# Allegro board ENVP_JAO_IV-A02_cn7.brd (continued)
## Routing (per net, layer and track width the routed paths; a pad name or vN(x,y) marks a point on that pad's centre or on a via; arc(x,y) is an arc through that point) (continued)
PS_1V8_SNUB: length 1.7
  TOP w0.508: C68.1 82.31,80.01 R58.2
PS_12_CS: length 14.4
  BOTTOM w0.254: R515.2 78.93,115.62 78.93,116.46 74.42,120.97 74.42,122.17 72.39,124.21 71.37,124.21 71.12,124.46 R94.1
  vias: v1(69.85,124.97) v1(69.85,124.33) v1(69.85,123.7) v1(71.5,127.76) v1(71.5,127.13) v1(71.5,126.49) v1(72.14,127.76) v1(72.77,127.76)
PS_12V_BIAS: length 11.4
  TOP w0.203: U8.21 75.2,113.62 74.78,114.05 74.55,114.05
  TOP w0.508: 74.55,114.05 73.53,115.06 C114.1 73.53,115.42 72.64,116.31 v1(72.64,116.33) ; R842.2 v1(78.17,118.36)
  L3-IN1 w0.508: v1(78.17,118.36) 77.28,117.47 73.79,117.47 v1(72.64,116.33)
PS_12V_BODE: length 1.1
  TOP w0.254: R92.2 C107.1
PS_12V_BOOT1: length 7.5
  TOP w0.203: U8.23 74.05,112.74
  TOP w0.508: 74.05,112.74 72.02,114.77 C111.2 72.02,115.68 71.63,116.08 71.63,118.44 D3.1
PS_12V_BOOT2: length 5.6
  TOP w0.203: U8.17 77.2,113.77 77.34,113.91 77.34,114.06
  TOP w0.508: C113.2 76.7,116.71 D2.1 76.14,116.27 76.39,116.01 76.39,114.94 76.77,114.55 77.09,114.55 77.34,114.3 77.34,114.06
PS_12V_COMP: length 3.4
  TOP w0.254: U8.6 77.2,108.98 77.34,108.84 77.34,107.65 C108.1 R92.1
PS_12V_CS: length 3.4
  TOP w0.254: v1(79.88,112.14) 79.87,112.13 U8.13
  BOTTOM w0.254: v1(79.88,112.14) 79.78,112.04 79.42,112.04 C109.1 78.99,112.47 78.99,113.12 R515.1
PS_12V_CSG: length 4.6
  TOP w0.254: U8.12 79.76,111.63 v1(79.88,111.51)
  BOTTOM w0.254: v1(79.88,111.51) 79.8,111.59 78.97,111.59 C109.2 78.49,112.47 78.49,113.06 R815.1
PS_12V_DITH: length 2.5
  TOP w0.254: C104.2 74.17,107.86 75.2,108.9 U8.2
PS_12V_FB: length 4.4
  TOP w0.254: R104.1 R103.1 80.59,108.51 80.01,109.09 78.46,109.09 78.2,109.35 U8.8
PS_12V_HDRV1: length 23.8
  TOP w0.203: U8.24 73.72,112.13 v1(73.25,112.6)
  TOP w0.508: v1(61.59,128.02) 61.16,127.58 R97.2
  BOTTOM w0.508: v1(73.25,112.6) 69.22,116.64 69.22,118.62 65.02,122.81 65.02,127.51 64.52,128.02 v1(61.59,128.02)
PS_12V_HDRV2: length 11.9
  TOP w0.203: 78.12,113.97 77.7,113.56 U8.16
  TOP w0.508: v1(77.09,115.19) 77.62,115.19 78.12,114.69 78.12,113.97 ; R99.2 79.88,122.62 v1(79.69,122.43)
  L3-IN1 w0.508: v1(77.09,115.19) 79.69,117.79 v1(79.69,122.43)
PS_12V_HG1: length 2.2
  TOP w0.508: Q12.1 61.98,127.38 61.27,126.67 R97.1
PS_12V_HG2: length 1.6
  TOP w0.508: R99.1 79.71,124.03 78.87,123.19 Q13.1
PS_12V_LDRV1: length 21.2
  TOP w0.203: 74.43,113.28 U8.22
  TOP w0.508: v1(74.17,113.54) 74.43,113.28 ; R98.2 v1(70.61,128.27)
  BOTTOM w0.508: v1(70.61,128.27) 68.58,128.27 67.82,127.51 67.82,123.19 68.2,122.81 68.45,122.81 68.83,122.43 68.83,120.52 70.23,119.13 70.23,117.49 v1(74.17,113.54)
PS_12V_LDRV2: length 10.3
  TOP w0.203: 76.7,113.79 U8.18
  TOP w0.254: v1(76.71,113.92) 76.7,113.91 76.7,113.79
  TOP w0.508: R100.2 72.2,120.71 v1(72.52,120.4)
  BOTTOM w0.508: v1(72.52,120.4) 74.3,118.62 74.3,115.19 75.56,113.92 v1(76.71,113.92)
PS_12V_LG1: length 2
  TOP w0.508: Q12.8 69.72,127.38 70.43,126.67 R98.1
PS_12V_LG2: length 1.3
  TOP w0.508: Q13.8 72.2,122.85 R100.1
PS_12V_MODE: length 2.8
  TOP w0.254: R102.1 73.03,107.48 74.7,109.16 U8.1
PS_12V_OUT: length 22.7
  TOP w0.254: 81.12,124.73 C117.1 81.13,124.49 82.55,123.06 85.47,123.06 87,121.54 87,117.86 81.03,111.89 R101.1 81.66,110.82 81.66,110.06 R103.2
  vias: v1(76.96,131.95) v1(76.96,131.32) v1(76.96,129.67) v1(76.96,129.03) v1(79.5,126.87) v1(79.5,126.24) v1(79.5,125.6) v1(79.5,124.97) v1(80.14,126.87) v1(80.14,126.24) v1(80.14,125.6) v1(80.14,124.97) v1(80.52,131.83) v1(80.52,130.05) v1(80.52,129.41) v1(80.52,128.14) v1(81.15,131.83) v1(81.15,130.05) v1(81.15,129.41) v1(81.15,128.14)
PS_12V_RT: length 2.3
  TOP w0.254: 75.7,108.79 U8.3
  TOP w0.508: R91.2 75.31,107.81 75.7,108.2 75.7,108.79
PS_12V_SLOPE: length 2.2
  TOP w0.254: C105.2 76.21,107.63 76.21,108.91 76.2,108.92 U8.4
PS_12V_SS: length 2.1
  TOP w0.254: U8.5 76.7,108.72 v1(76.83,108.58)
  BOTTOM w0.254: C106.2 76.35,108.58 v1(76.83,108.58)
PS_12V_SW1: length 13
  TOP w0.203: 73.06,111.84 73.27,111.63 U8.25
  TOP w0.508: 73.06,111.84 70.47,114.43 C111.1 70.47,116.34 69.72,117.09 69.72,118.87 67.92,120.68 R69.1
PS_12V_SW2: length 11
  TOP w0.203: 78.4,113.36 78.31,113.28 U8.15
  TOP w0.508: 78.4,113.36 78.49,113.36 78.88,113.76 C113.1 78.88,116.4 76.96,118.31 76.96,119.89 76.45,120.4 74.68,120.4 74.17,120.9
PS_12V_VCC: length 6.3
  TOP w0.203: 75.5,114.05 75.5,113.86 75.7,113.65 U8.20
  TOP w0.508: D3.2 74.74,118.24 D2.2 74.74,115.62 C112.1 74.79,114.76 75.5,114.05
PS_12V_VIN: length 6
  TOP w0.254: 73.2,110.45 73.38,110.63 U8.27
  TOP w0.508: R93.2 71.36,107.98 C110.1 71.5,107.96 73.2,109.66 73.2,110.45
PS_12V_VIN_D: length 1.7
  TOP w0.508: D1.1 69.79,105.34 69.6,105.54 R93.1
PS_12V_VOSNS: length 2.3
  TOP w0.254: U8.9 80.61,110.13 R101.2
PS_20_CS: length 13
  BOTTOM w0.254: R479.1 36.13,110.82 36.13,111.3 38.42,113.59 38.42,115.95 37.78,116.59 34.61,116.59 34.23,116.97 R698.1 34.23,118.61
  vias: v1(31.81,119.38) v1(31.81,118.75) v1(31.81,118.11) v1(31.81,117.41) v1(34.16,121.16) v1(34.8,121.16) v1(35.43,121.16) v1(36.07,121.16) v1(36.64,119.38) v1(36.64,118.75) v1(36.64,118.11) v1(36.64,117.41) v1(37.08,121.16) v1(37.72,121.16)
PS_20V_BIAS: length 16.4
  TOP w0.203: U124.21 31.1,108.6 30.56,109.14
  TOP w0.508: 30.56,109.14 30.18,109.52 C510.1 30.29,110.43 v1(30.73,110.87) ; R841.2 41.27,113.16 v1(40.64,113.79)
  L6-IN2 w0.508: v1(40.64,113.79) 37.72,110.87 v1(30.73,110.87)
PS_20V_BODE: length 1.1
  TOP w0.254: C513.1 R688.2
PS_20V_BOOT1: length 5.8
  TOP w0.203: 29.95,107.85 U124.23
  TOP w0.508: D28.1 27.7,112.14 C506.2 27.7,110.1 29.95,107.85
PS_20V_BOOT2: length 8
  TOP w0.203: 33.27,109.09 33.1,108.92 U124.17
  TOP w0.508: 33.27,109.09 34.54,110.36 36.94,110.36 C507.2 37.07,111.25 D29.1
PS_20V_COMP: length 5.1
  TOP w0.254: R688.1 35.89,102.23 C512.1 35.13,103 33.78,103 33.1,103.68 U124.6
PS_20V_CS: length 4.7
  TOP w0.254: U124.13 35.78,107.1 36.2,106.68 v1(36.2,106.55)
  BOTTOM w0.254: v1(36.2,106.55) 36.13,106.62 36.13,106.92 C505.2 36.13,107.96 36.13,108.38 R479.2
PS_20V_CSG: length 3.8
  TOP w0.254: v1(35.56,106.55) 35.52,106.6 U124.12
  BOTTOM w0.254: v1(35.56,106.55) 35.62,106.62 35.62,106.92 C505.1 35.62,107.96 35.62,108.32 R513.2
PS_20V_DITH: length 2.4
  TOP w0.254: C497.2 30.48,103.25 31.1,103.87 U124.2
PS_20V_FB: length 4.4
  TOP w0.254: R697.1 36.7,103.56 36.7,104.47 R694.2 36.32,104.65 35.94,104.27 34.28,104.27 U124.8
PS_20V_HDRV1: length 22.8
  TOP w0.203: v1(29.21,107.57) 29.21,107.37 29.48,107.1 U124.24
  TOP w0.508: v1(24.13,125.22) 23.88,125.48 R689.1
  BOTTOM w0.508: v1(24.13,125.22) 24.13,110.62 27.18,107.57 v1(29.21,107.57)
PS_20V_HDRV2: length 41.2
  TOP w0.203: U124.16 33.6,108.53 34.04,108.97 34.16,108.97
  TOP w0.508: R692.1 v1(47.88,138.18) ; v1(37.47,109.47) 34.67,109.47 34.16,108.97
  L3-IN1 w0.508: v1(47.88,138.18) 48.77,137.29 48.77,127 48.26,126.49 44.45,126.49 43.94,125.98 43.94,115.95 v1(37.47,109.47)
PS_20V_HG1_2: length 3.1
  TOP w0.508: R689.2 23.88,128.27 23.25,128.9 Q64.1
PS_20V_HG2: length 1.8
  TOP w0.508: R692.2 46.19,138.09 Q68.1
PS_20V_LDRV1: length 16.9
  TOP w0.203: v1(30.15,108.58) 30.35,108.58 30.6,108.34 U124.22
  TOP w0.508: v1(33.15,121.16) 33.15,120.47 R690.1
  BOTTOM w0.508: v1(33.15,121.16) 30.86,121.16 29.72,120.02 29.72,109.02 v1(30.15,108.58)
PS_20V_LDRV2: length 8.8
  TOP w0.203: U124.18 32.6,109.05 32.64,109.09
  TOP w0.508: R691.1 35.56,114.99 35.56,111.51 35.18,111.12 34.29,111.12 32.64,109.47 32.64,109.09
PS_20V_LG1: length 1.4
  TOP w0.508: R690.2 32.25,120.46 U126.4
PS_20V_LG2: length 1.9
  TOP w0.508: R691.2 36.99,116.15 Q65.4
PS_20V_MODE: length 2.7
  TOP w0.254: R693.1 29.34,102.87 30.6,104.13 U124.1
PS_20V_RT: length 2.1
  TOP w0.254: 31.6,103.76 U124.3
  TOP w0.508: 31.6,103.76 31.6,102.34 R687.2
PS_20V_SLOPE: length 2.4
  TOP w0.254: U124.4 32.1,103.89 32.11,103.88 32.11,102.92 32.72,102.31 C511.1
PS_20V_SS: length 3.2
  TOP w0.254: U124.5 32.6,103.57 34.04,102.13 C509.2
PS_20V_SW1: length 11
  TOP w0.203: U124.25 29.17,106.6 28.96,106.81
  TOP w0.508: R844.1 25.15,113.91 25.15,111.24 C506.1 26.15,109.61 28.96,106.81
PS_20V_SW2: length 11.6
  TOP w0.203: 34.29,108.33 34.21,108.25 U124.15
  TOP w0.508: 34.29,108.33 34.92,108.33 35.18,108.58 37.72,108.58 38.23,109.09 38.23,110.1 C507.1 38.99,110.49 39.75,111.25 39.75,114.01 C620.2
PS_20V_VCC: length 6.9
  TOP w0.203: 31.37,109.09 31.5,108.97 31.5,108.58 31.6,108.48 U124.20
  TOP w0.508: 31.37,109.09 31.37,110.38 C514.1 31.5,110.5 31.5,112.15 D28.2 32,112.65 D29.2
PS_20V_VOSNS: length 2.4
  TOP w0.254: U124.9 35.12,105.1 35.81,105.79 R696.1
RS232_RD1: length 4.2
  BOTTOM w0.102: 23.68,95.21 23.4,95.21 23.24,95.38 23.24,96.25 22.91,96.58 22.91,97.2 22.48,97.62 22.01,97.62 R610.1
RS232_RD2: length 3.7
  BOTTOM w0.102: 23.68,79.72 23.4,79.72 23.24,79.88 23.24,80.75 22.25,81.75 22.01,81.75 R665.1
RS232_TD1: length 2.3
  BOTTOM w0.102: R612.1 21.56,94.21 23.68,94.21
RS232_TD2: length 2.3
  BOTTOM w0.102: 23.68,78.72 21.62,78.72 R667.1
RS485_D1-: length 4.4
  BOTTOM w0.102: R608.1 22.01,97.83 22.57,97.83 23.11,97.28 23.11,96.66 23.38,96.39 24.26,96.39 24.42,96.23 24.42,95.96
RS485_D2-: length 3.9
  BOTTOM w0.102: R663.1 22.01,81.95 22.33,81.95 23.38,80.9 24.26,80.9 24.42,80.74 24.42,80.46
RTS1: length 26.7
  TOP w0.102: v1(21.84,91.82) 21.84,91.42 D52.2 19.15,89.79 18.9,90.04 18.9,91.53 17.72,92.71 14.73,92.71 12.06,90.04 12.06,86.49 10.03,84.45 9.14,84.45 6.8,86.8 CN35.16
  BOTTOM w0.102: 23.68,92.21 22.24,92.21 v1(21.84,91.82)
RTS2: length 20.9
  TOP w0.102: v1(21.97,75.95) 21.97,74.8 21.08,73.91 D57.2 15.37,78.76 15.37,85.2 CN35.7
  BOTTOM w0.102: 23.68,76.72 22.74,76.72 v1(21.97,75.95)
RX1/D1+: length 20.9
  TOP w0.102: CN35.11 9.64,89.42 9.74,89.52 10.56,89.52 14.51,93.47 17.27,93.47 18.54,94.74 18.54,97.63 18.75,97.84 18.92,97.84 19.27,97.5 19.27,96.3 19.43,96.14 D53.2 20.21,97.14 v1(19.94,97.41)
  BOTTOM w0.102: v1(19.94,97.41) 20.15,97.62 20.52,97.62 20.62,97.52 R610.2
RX2/D2+: length 15.7
  TOP w0.102: v1(19.77,81.53) 20.21,81.09 D58.2 19.43,80.26 19.18,80.52 19.18,81.56 19.08,81.66 18.8,81.66 18.54,81.92 18.54,86.03 17.84,86.73 17.84,89.09 17.41,89.52 16.65,89.52 16.55,89.42 CN35.2
  BOTTOM w0.102: v1(19.77,81.53) 19.99,81.75 20.15,81.75 R665.2
SNN_EFM8SB10_P0_5: length 3.2
  BOTTOM w0.102: TP49.1 95,64.52 94.51,65 92.17,65 92.16,65.01
SNN_USBC2_MUX_CTRL_N: length 2.5
  TOP w0.102: R559.2 52.25,70.41 52.68,70.85 U107.28
SNN_VBUS_MON_P2: length 3.1
  TOP w0.102: R848.1 56.7,76.96 54.79,75.05 U107.37
SNN_VCONN_MON_P2: length 3.3
  TOP w0.254: U107.25 51.19,70.83 49.32,68.96 R849.1
SP339_5V: length 33.6
  TOP w0.254: 16.58,62.36 17.26,62.36 17.27,62.36 v1(17.4,62.36)
  TOP w0.381: 29.67,91.19 30.58,91.19 v1(30.6,91.21)
  BOTTOM w0.254: 24.19,73.6 24.42,73.82 24.42,74.48 ; 29.66,91.21 v1(30.6,91.21) ; 24.42,89.97 24.42,88.94 v1(24,88.52) ; C454.2 28.7,97.79 27.92,97.01 27.92,95.96 ; 24.92,95.96 24.92,97.25 v1(24.64,97.54) ; v1(30.61,75.41) 30.3,75.72 29.66,75.72 ; C473.2 24.92,82.57 24.92,80.46 ; 27.92,80.46 v1(27.92,81.39)
  BOTTOM w0.508: C454.2 28.24,98.22 28.07,98.04 v1(27.94,98.04) ; v1(24.13,82.17) 24.56,82.6 C473.2 ; v1(17.4,62.36) 16.76,62.36 16.65,62.24 16.51,62.24 16.46,62.29 16.46,63.63 18.92,63.63 19.81,64.52 19.81,69.98 21.34,71.5 22.23,71.5 22.73,72.01 22.73,73.15 v1(22.99,73.41) 24,73.41 24.19,73.6
  vias: v1(30.61,81.28) v1(30.61,80.64) v1(31.24,81.28) v1(31.24,80.64)
SP339_UART2_RTS: length 80.7
  TOP w0.102: R304.2 89.48,97.92 89.48,96.72 v1(89.79,96.42)
  L6-IN2 w0.089: v1(43.94,78.49) 43.94,79.06 44.22,79.34 47.77,79.34 48.11,78.99 52.32,78.99 52.96,78.36 56.19,78.36 59.21,75.33 86.14,75.33 87.22,76.41 89.3,76.41 89.97,77.08 89.97,79.91 90.4,80.35 90.4,84.52 89.12,85.81 89.12,89.61 88.44,90.29 88.44,92.88 89.15,93.6 89.15,93.85 88.98,94.03 88.98,95.07 89.79,95.89 v1(89.79,96.42)
  BOTTOM w0.102: 37.01,75.93 39.35,75.93 39.37,75.95 40.77,75.95 41.4,76.58 42.55,76.58 43.94,77.98 v1(43.94,78.49)
SP339_UART2_RX: length 76.7
  TOP w0.102: v1(88.65,93.73) 91.24,93.73 R625.2
  L6-IN2 w0.089: v1(88.65,93.73) 88.12,93.2 88.12,90.15 88.8,89.47 88.8,85.68 89.03,85.45 89.03,77.49 88.27,76.73 87.09,76.73 86.01,75.65 59.35,75.65 55.68,79.31 48.25,79.31 47.9,79.65 44.09,79.65 43.62,79.19 43.62,78.8 v1(43.31,78.49)
  BOTTOM w0.102: 37.01,76.33 37.87,76.33 38.89,77.34 40.77,77.34 41.45,78.03 42.85,78.03 v1(43.31,78.49)
SP339_UART2_TX: length 77.3
  TOP w0.102: R624.2 91.74,93.09 v1(89.28,93.09)
  L6-IN2 w0.089: v1(89.28,93.09) 89.43,92.94 89.43,85.94 90.72,84.66 90.72,80.21 90.28,79.78 90.28,76.95 89.43,76.09 87.35,76.09 86.27,75.01 59.08,75.01 56.65,77.44 55.84,77.44 55.24,78.04 43.05,78.04 42.8,78.3 42.8,78.74 42.29,79.25 v1(42.27,79.25)
  BOTTOM w0.102: 37.01,76.73 37.74,76.73 38.17,77.16 38.17,77.54 39.24,78.61 40.69,78.61 41.33,79.25 v1(42.27,79.25)
SRC_ON_D: length 3.9
  TOP w0.254: Q20.1 62.93,103.75 62.93,102.72 Q19.3 62.79,102.73 R120.2
SRC_SW_G: length 7.3
  TOP w0.508: R120.1 61.42,103.76 C621.2 v1(60.2,105.16) 60.2,105.87 R119.2 60.2,106.22 Q21.4
  BOTTOM w0.508: v1(60.2,105.16) 60.35,105 C126.2
SYS_RST_IN_N: length 131.8
  TOP w0.102: v1(8.64,41.27) 7.62,41.27 6.55,40.21 6.48,40.21 ; v1(87.76,71.12) 90.14,71.12 90.65,70.61 94.64,70.61 v1(97.84,73.81)
  L6-IN2 w0.089: v1(8.64,41.27) 10.67,43.31 10.67,45.86 12.57,47.76 12.57,64.36 22.57,74.36 23.18,74.36 24.68,75.86 31.84,75.86 32.55,75.15 34.32,75.15 35.13,74.34 42.52,74.34 43.39,73.47 47.4,73.47 47.4,73.47 47.75,73.47 47.75,73.47 48.01,73.21 48.01,71.78 48.91,70.88 49.2,70.88 49.2,70.89 55.48,70.89 56.43,69.93 68.21,69.93 70.42,72.14 86.73,72.14 v1(87.76,71.12)
  BOTTOM w0.102: v1(97.84,73.81) 97.82,73.79 97.41,73.79 97.1,74.09 97.1,76 96.79,76.31 96.79,77.48 97.36,78.05 97.36,78.87 ; Q40.1 86.35,70.6 86.87,71.12 v1(87.76,71.12)
SYS_RST_IN_Q: length 5
  BOTTOM w0.102: Q41.1 89.14,68.82 88.33,68.01 Q40.3 87,67.06 87.2,66.85 R469.2
TX1: length 18.5
  TOP w0.102: v1(21.84,92.58) 21.46,92.96 D51.2 14.66,92.96 11.84,90.14 11.84,86.58 10.73,85.47 CN35.12
  BOTTOM w0.102: R612.2 21.46,92.96 v1(21.84,92.58)
TX2: length 13
  TOP w0.102: CN35.3 17.65,84.37 17.65,78.61 19.18,77.09 D56.2 21.72,77.09 v1(21.84,76.96)
  BOTTOM w0.102: R667.2 21.46,77.34 v1(21.84,76.96)
UPHY0_RX4_N:
  vias: v2(164.09,103.66) v3(164.09,103.66) v4(163.47,103.71) v5(122.76,95.02) v6(122.76,95.02)
UPHY0_RX4_P:
  vias: v2(164.09,103.15) v3(164.09,103.15) v4(163.47,103.1) v5(122.25,95.02) v6(122.25,95.02)
UPHY0_RX5_N:
  vias: v2(165.14,101.9) v3(165.14,101.9) v4(120.2,90.05) v5(120.25,90.52) v6(120.25,90.52)
UPHY0_RX5_P:
  vias: v2(165.14,101.39) v3(165.14,101.39) v4(120.81,90.05) v5(120.76,90.52) v6(120.76,90.52)
UPHY0_SF_PCIE1_CLK_N:
  vias: v2(154.58,65.46) v3(154.58,65.46) v4(115.9,79.76) v5(107.38,94.68) v6(107.38,94.68)
UPHY0_SF_PCIE1_CLK_P:
  vias: v2(154.58,65.97) v3(154.58,65.97) v4(115.29,79.76) v5(106.88,94.68) v6(106.88,94.68)
UPHY0_TX5_N:
  vias: v2(170.98,100.44) v3(170.98,100.44) v4(165.65,106.16) v5(122.25,101.02) v6(122.25,101.02)
UPHY0_TX5_P:
  vias: v2(170.98,99.94) v3(170.98,99.94) v4(165.65,106.77) v5(122.76,101.02) v6(122.76,101.02)
UPHY1_REFCLK0_N:
  vias: v5(124.19,99.1) v5(154.56,128.02) v6(124.19,99.1) v6(154.56,128.02)
UPHY1_REFCLK0_P:
  vias: v5(124.7,99.1) v5(155.07,128.02) v6(124.7,99.1) v6(155.07,128.02)
UPHY2_REFCLK2_N:
  vias: v2(124.11,96.14) v3(124.11,96.14) v4(124.34,97.61) v5(126.25,98) v6(126.25,98)
UPHY2_REFCLK2_P:
  vias: v2(124.62,96.14) v3(124.62,96.14) v4(124.94,97.61) v5(126.76,98) v6(126.76,98)
UPHY_RX10_N:
  vias: v2(163.81,98.9) v3(163.81,98.9) v4(142.8,91.02) v5(142.25,92.01) v6(142.25,92.01)
UPHY_RX10_P:
  vias: v2(163.81,98.39) v3(163.81,98.39) v4(143.41,91.02) v5(142.76,92.01) v6(142.76,92.01)
UPHY_RX11_N:
  vias: v2(163.62,95.9) v3(163.62,95.9) v4(143.31,97.02) v5(143.36,96.53) v6(143.36,96.53)
UPHY_RX11_P:
  vias: v2(163.62,95.39) v3(163.62,95.39) v4(143.92,97.02) v5(143.87,96.53) v6(143.87,96.53)
UPHY_TX6_N:
  vias: v2(116.11,45.55) v3(116.11,45.55) v4(116.06,46.5) v5(136.78,97.66) v6(136.78,97.66)
UPHY_TX6_P:
  vias: v2(116.62,45.55) v3(116.62,45.55) v4(116.67,46.5) v5(136.27,97.66) v6(136.27,97.66)
UPHY_TX9_N:
  vias: v2(94.81,136.51) v3(94.81,136.51) v4(94.86,136.06) v5(140.6,102.02) v6(140.6,102.02)
UPHY_TX9_P:
  vias: v2(94.3,136.51) v3(94.3,136.51) v4(94.25,136.06) v5(140.09,102.02) v6(140.09,102.02)
USB2_1_N:
  vias: v7(144.84,94.93)
USB2_1_P:
  vias: v7(144.18,94.93)
USB2_3_N:
  vias: v2(83.36,39.3) v3(83.36,39.3) v4(83.82,39.35) v5(144.75,99.06) v6(144.75,99.06)
USB2_3_P:
  vias: v2(83.36,38.79) v3(83.36,38.79) v4(83.82,38.74) v5(144.25,99.06) v6(144.25,99.06)
USBC1_CC1_DUT: length 6.5
  TOP w0.203: v1(46.23,80.77) 46.18,80.72 C422.1 46.81,77.98 49.53,77.98 49.68,77.82 U107.9
USBC1_CC2_DUT: length 5
  TOP w0.203: U107.7 50.68,78.12 52.2,79.63 C423.1 52.2,79.88 51.56,80.52 v1(51.56,81.41)
USBC1_MUX_CTRL_N: length 4.4
  TOP w0.102: v1(55.24,69.72) 55.24,69.01 R558.2 54.56,69.6 53.72,69.6 53.47,69.85 53.47,70.61 53.19,70.89 U107.29
USBC1_ORIENTATION: length 0.9
  TOP w0.102: v1(47.57,73.05) U107.18
USBC1_VBUS: length 5.1
  TOP w0.508: R555.1 41.27,75.18 39.5,73.41 v1(37.97,73.41)
  vias: v1(30.48,67.18) v1(30.48,66.55) v1(31.11,67.18) v1(31.11,66.55) v1(31.75,67.18) v1(31.75,66.55) v1(32.46,67.18) v1(33.15,67.18) v1(33.78,67.18) v1(33.78,66.55) v1(39.12,102.23) v1(39.12,101.6) v1(39.75,102.23) v1(39.75,101.6) v1(176.75,114.68) v1(176.75,114.05) v1(177.38,114.68) v1(177.38,114.05) v1(177.74,113.47) v1(178.02,114.68) v1(178.02,114.05) v1(178.37,113.47) v1(178.69,114.68) v1(178.69,114.05) v1(179.63,107.29) v1(179.63,106.65) v1(180.34,107.94) v1(180.28,107.29) v1(180.28,106.65) v1(180.57,106.08) v1(180.92,107.25) v1(180.92,106.62) v1(181.48,110.32) v1(181.56,107.26) v1(181.57,106.62) v1(182.11,110.12)
VCONN_MON_P1: length 4.6
  TOP w0.102: R553.2 R554.1 C424.1 46.33,72.54 U107.19
XRES: length 4.7
  TOP w0.102: R552.2 C421.1 46.48,76.33 47.12,76.96 49.02,76.96 49.19,77.13 U107.10
N7364585: length 3.1
  TOP w0.254: R31.1 R32.2 68.58,82.5 U2.11
N7364615: length 5
  TOP w0.254: U2.16 69.84,86.63
  TOP w0.508: R30.2 72.82,87.43 C46.1 72.54,87.5 70.93,87.5 70.05,86.63 69.84,86.63
N7364639: length 2.3
  TOP w0.254: C58.1 R44.1 R43.2
N7364653: length 4.1
  TOP w0.254: U2.9 67.58,83.96 67.44,83.82
  TOP w0.508: R46.2 65.98,82.37 C60.1 66.55,82.56 66.55,82.93 67.44,83.82
N7364665: length 5.1
  TOP w0.254: U2.12 69.08,84.09 70.79,82.37 C59.1 R47.1 R45.2
N7364675: length 3
  TOP w0.254: R48.1 70.61,83.44 69.69,84.37 U2.13
N7364759: length 2
  TOP w0.508: R33.1 66.55,90.55 v1(66.29,90.81)
  BOTTOM w0.508: C47.1 66.79,90.31 v1(66.29,90.81)
N7364853: length 9.6
  TOP w0.254: R48.2 72.71,83.55 R49.1 73.91,83.06 73.53,82.68 C62.1 74.3,81.42 74.3,79.24 C56.2 73.53,78.47 C58.2 R44.2
N7364927: length 5.6
  TOP w0.254: 66.16,85.48 U2.7
  TOP w0.762: R40.2 63.75,87.76 66.04,85.48 66.16,85.48
N7364931: length 3.8
  TOP w0.254: U2.2 68.58,87.69 69.98,89.09 C55.1 R39.2
N7365093: length 23.1
  TOP w0.254: C56.1 71.75,78.74 69.29,76.28 65.46,76.28 62.48,79.25 62.48,88.02 R42.2
N7365097: length 2
  TOP w0.508: C57.1 61.99,90.22 61.02,91.19 R41.2
N7366211: length 2.5
  TOP w0.254: U2.4 67.58,87.36 67.44,87.5
  TOP w0.508: 67.44,87.5 67.44,87.76 66.55,88.65 R33.2
N7366215: length 3.4
  TOP w0.254: 66.8,87 66.8,86.64 U2.5
  TOP w0.762: R35.2 65.28,88.52 66.8,87
N7366231: length 2.3
  TOP w0.254: 68.08,87.88 U2.3
  TOP w0.508: 68.08,87.88 68.08,88.82 R36.2
N7371396: length 1.8
  TOP w0.254: U3.8 81.14,83.55 81.28,83.69
  TOP w0.508: C66.2 81.41,83.95 81.28,83.82 81.28,83.69
N7372642: length 17.3
  TOP w0.254: R55.1 86.74,87.25 88.77,85.22 88.77,77.85 88.52,77.6 86.87,77.6
  vias: v1(83.69,78.93) v1(83.69,78.17) v1(83.69,77.41)
N7382435: length 2.4
  TOP w0.254: 68.57,66.15 68.57,66.41 69.6,67.44 C82.2
N7382555: length 22
  TOP w0.254: R66.1 83.77,70.41 84.33,69.85 84.33,65.53 83.06,64.26 R64.1
N7394854:
  vias: v1(126.82,43.64)
N7434344: length 5
  TOP w0.102: Q14.6 70.37,112.26 ; 70.37,112.26 70.48,112.14 70.76,112.14 70.87,112.24 Q14.5 ; 70.37,112.26 69.85,111.74 69.85,111.12 69.09,110.36 69.09,109.65 R107.2
N7802848: length 5.5
  TOP w0.254: C380.2 R705.2 93.14,87.76 93.14,85.9 92.71,85.47 92.71,84.71
N7804391: length 2.1
  BOTTOM w0.102: R462.1 90.73,77.55 90.93,77.34 90.93,76.71 91.17,76.47 U77.6
N7854424: length 2.3
  BOTTOM w0.102: R521.1 53.54,83.57 52.96,84.15 52.96,84.84 53.21,85.08 U97.4
N7855347: length 3.2
  BOTTOM w0.102: R523.1 51.05,83.36 51.05,84.84 50.79,85.1 U99.4
N7856574: length 2.7
  TOP w0.102: U102.6 49.13,87.64 48.9,87.88 48.13,87.88 47.5,87.25 R525.2
N7893694: length 1.5
  TOP w0.102: U104.6 58.94,81.55 59.18,81.79 59.89,81.79 R526.2
N8090559: length 2.3
  BOTTOM w0.102: C456.2 26.31,96.7 26.42,96.6 26.42,95.96
N8090595: length 2.3
  BOTTOM w0.102: 27.42,95.96 27.42,97.22 27.23,97.41 C456.1
N8090599: length 3.6
  BOTTOM w0.102: C459.2 25.83,98.83 25.83,96.62 25.92,96.53 25.92,95.96
N8090635: length 6.3
  BOTTOM w0.102: 28.42,95.96 28.42,96.97 29.31,97.87 29.31,99.44 28.98,99.77 27.69,99.77 C459.1
N8090819: length 2.3
  BOTTOM w0.102: 25.92,89.97 25.92,87.82 R620.1
N8148227: length 1.1
  BOTTOM w0.254: R649.2 R653.1
N8148339: length 1.4
  TOP w0.254: C476.2 84.8,108.32 U117.8
N8148459: length 14.7
  TOP w0.254: 90.04,111.76 90.04,112.65 88.77,113.92 84.71,113.92 82.93,112.14 82.93,108.58 82.3,107.95 R655.1
N8158949: length 2.2
  BOTTOM w0.102: R674.1 26.16,73.03 25.92,73.27 25.92,74.48
N8239387: length 2.2
  TOP w0.508: D31.1 24.96,102.33 25.78,103.15 R701.2
N8694423: length 2
  BOTTOM w0.508: R801.2 20.24,102.95 20.02,103.16 Q73.4
N10120133: length 2.1
  TOP w0.508: C605.1 69.75,122.19 R69.2
N10120570: length 1.5
  TOP w0.508: R843.2 76.17,121.79 C618.1
N10120736: length 1.5
  TOP w0.508: C619.1 29.21,114.78 R844.2
N10120879: length 1.5
  TOP w0.508: C620.1 41.5,114.94 R845.2

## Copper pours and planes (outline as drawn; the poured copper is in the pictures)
3V3_AO on TOP (solid shape): 83.82,68.33 83.82,65.79 83.57,65.53 80.64,65.53 80.39,65.79 80.39,68.33 80.64,68.58 83.57,68.58
3V3_AO on BOTTOM (solid shape): 83.82,68.33 83.82,66.42 83.69,66.29 83.69,65.79 83.44,65.53 80.64,65.53 80.39,65.79 80.39,68.33 80.64,68.58 83.57,68.58
3V3_AO on L4-VCC1: 103.74,82.04 117.5,82.04 117.86,81.68 117.86,78.49 117.88,78.39 117.93,78.31 121.74,74.5 121.82,74.44 121.92,74.42 129.05,74.42 134.49,68.98 134.49,56.9 134.51,56.8 134.57,56.72 138.12,53.16 138.21,53.11 138.3,53.09 156.49,53.09 159.89,49.68 159.89,47.98 159.28,47.37 154.16,47.37 152.33,49.2 152.24,49.26 152.15,49.28 148.19,49.28 148.01,49.46 147.93,49.51 147.83,49.53 94.49,49.53 94.39,49.51 94.31,49.46 93.37,48.51 90.02,48.51 89.66,48.87 89.66,58.42 89.64,58.52 89.59,58.6 88.57,59.62 88.49,59.67 88.39,59.69 80.88,59.69 80.01,60.56 80.01,65.93 85.83,71.75 88.52,71.75 88.62,71.77 88.7,71.83 95.61,78.74 97.54,78.74 97.63,78.76 97.72,78.81 100.44,81.53 103.12,81.53 103.22,81.55 103.3,81.61
3V3_AO_SW on TOP (solid shape): 74.68,68.33 74.68,63.75 74.42,63.5 69.34,63.5 69.09,63.75 69.09,64.52 68.83,64.77 67.56,64.77 67.56,65.02 69.34,65.02 69.6,65.28 69.6,65.53 70.1,66.04 70.61,66.04 70.87,66.29 70.87,67.82 71.63,68.58 74.42,68.58
3V3_PVDD on TOP (solid shape): 65.66,84.96 66.42,84.96 66.67,85.22 67.06,85.22 67.18,85.09 67.18,84.2 66.93,83.95 66.04,83.95 65.15,83.06 64.77,83.06 64.64,83.19 64.64,83.69 64.39,83.95 64.39,85.22 64.64,85.47 65.15,85.47
5V_AO on TOP (solid shape): 99.06,58.55 99.06,54.1 98.68,53.72 98.68,52.45 98.55,52.32 98.42,52.32 98.3,52.45 98.3,52.96 97.79,53.47 97.79,53.85 96.52,55.12 96.52,58.55 96.65,58.67 98.93,58.67
5V_AO on TOP (solid shape): 60.83,61.47 60.83,58.17 60.58,57.91 52.96,57.91 52.7,58.17 52.7,61.47 52.96,61.72 60.58,61.72
5V_AO on TOP (solid shape): 65.53,68.58 65.53,66.8 66.8,65.53 68.07,65.53 68.07,65.28 67.56,65.28 67.31,65.02 62.48,65.02 62.23,65.28 62.23,68.58 62.48,68.83 65.28,68.83
5V_AO on BOTTOM (solid shape): 66.04,68.58 66.04,65.28 65.79,65.02 62.48,65.02 62.23,65.28 62.23,68.58 62.48,68.83 65.79,68.83
5V_AO on BOTTOM (solid shape): 99.57,58.17 99.57,54.99 99.31,54.74 96.77,54.74 96.52,54.99 96.52,58.17 96.77,58.42 99.31,58.42
5V_AO on BOTTOM (solid shape): 60.83,61.47 60.83,58.55 60.58,58.29 52.96,58.29 52.7,58.55 52.7,61.47 52.96,61.72 60.58,61.72
5V_AO on L4-VCC1: 45.06,81.53 47.14,81.53 48.08,80.59 48.16,80.54 48.26,80.52 57.55,80.52 59,79.07 59.08,79.01 59.18,78.99 61.47,78.99 61.57,79.01 61.65,79.07 63.86,81.28 65.43,81.28 66.17,80.54 66.17,78.36 66.19,78.26 66.24,78.18 68.4,76.02 68.48,75.97 68.58,75.95 70,75.95 70.36,75.59 70.36,55.99 68.6,54.23 57.89,54.23 56.13,55.99 56.13,73.43 56.69,73.99 56.75,74.07 56.77,74.17 56.77,76.07 56.75,76.17 56.69,76.25 55.04,77.9 54.96,77.96 54.86,77.98 47.1,77.98 44.7,80.37 44.7,81.17
5V_AO on L5-VCC2: 63.1,68.45 73.17,68.45 79.58,62.05 79.66,62 79.76,61.98 86.51,61.98 88.72,59.76 88.8,59.71 88.9,59.69 105.66,59.69 105.76,59.71 105.84,59.76 106.53,60.45 130.96,60.45 133.1,58.31 133.1,57.4 133.12,57.31 133.17,57.22 135.46,54.94 135.54,54.88 135.64,54.86 144.27,54.86 144.37,54.88 144.45,54.94 144.89,55.37 145.44,55.37 145.87,54.94 145.95,54.88 146.05,54.86 149.75,54.86 150.19,54.43 150.27,54.38 150.37,54.36 151.02,54.36 151.64,53.74 151.64,49.89 151.02,49.28 122.03,49.28 118.8,52.5 118.72,52.56 118.62,52.58 112.9,52.58 112.81,52.56 112.72,52.5 110.77,50.55 78.34,50.55 74.98,53.9 74.9,53.96 74.8,53.98 58.65,53.98 56.01,56.62 56.01,61.36
5V_DISCHG_D on TOP (solid shape): 54.36,68.07 54.36,65.79 54.1,65.53 48.51,65.53 48.26,65.79 48.26,68.07 48.51,68.33 54.1,68.33
+3V3A_L on TOP (solid shape): 49.78,99.82 49.78,90.93 49.53,90.68 45.21,90.68 44.45,89.92 41.91,89.92 41.66,90.17 41.66,99.82 41.91,100.08 49.53,100.08
+3V3A_L on BOTTOM (solid shape): 49.78,99.82 49.78,91.19 49.53,90.93 45.47,90.93 45.21,90.68 44.96,90.68 43.94,91.69 41.91,91.69 41.66,91.95 41.66,99.82 41.91,100.08 49.53,100.08
AGND on L2-GND1, L4-VCC1, L5-VCC2, L7-GND2: 179.81,26.16 182.52,26.16 182.64,26.04 182.63,25.97 182.63,25.91 182.63,24.13 182.66,23.94 182.77,23.77 183.9,22.65 183.9,16.97 181.91,14.99 181.1,14.99 180.91,14.95 180.74,14.84 179.98,14.08 179.87,13.91 179.83,13.72 179.83,10.62 179.11,9.91 175.07,9.91 174.99,9.83 174.95,9.8 174.9,9.76 173.76,8.61 173.72,8.57 173.68,8.52 173.61,8.45 173.61,1.67 173.57,1.63 172.96,1.02 172.42,1.02 172.23,1.21 172.23,13.38 172.23,13.41 171.21,14.73 169.59,14.31 165.29,14.31 163.62,14.71 162.65,13.3 162.65,9.82 163.32,9.14 163.32,7.49 162.65,6.82 162.65,1.31 162.35,1.02 161.75,1.02 161.29,1.48 161.29,18.03 161.25,18.23 161.14,18.39 160.27,19.26 160.27,22.14 160.48,22.35 169.93,22.35 170.43,21.84 172.11,21.84 172.34,21.61 172.34,20.32 172.36,20.22 172.41,20.14 172.79,19.76 172.88,19.7 172.97,19.68 176.66,19.68 176.75,19.7 176.84,19.76 177.22,20.14 177.27,20.22 177.29,20.32 177.29,23.52 177.4,23.62 178.94,23.62 179.04,23.64 179.12,23.7 179.5,24.08 179.56,24.16 179.58,24.26 179.58,25.93
GND on TOP (solid shape): 21.84,105.92 21.84,103.89 21.59,103.63 19.81,103.63 19.56,103.89 19.56,105.92 19.81,106.17 21.59,106.17
GND on TOP (solid shape): 68.83,114.3 68.83,109.98 68.58,109.73 64.77,109.73 64.52,109.98 64.52,114.3 64.77,114.55 68.58,114.55
GND on TOP (solid shape): 181.36,29.72 181.36,26.92 181.1,26.67 179.07,26.67 178.82,26.92 178.82,29.72 179.07,29.97 181.1,29.97
GND on TOP (solid shape): 35.05,116.33 35.05,114.3 34.8,114.05 33.27,114.05 33.02,113.79 31.75,113.79 31.5,114.05 31.5,116.08 32,116.59 34.8,116.59
GND on TOP (solid shape): 41.15,99.82 41.15,94.49 40.89,94.23 38.23,94.23 37.85,93.85 37.85,90.55 37.59,90.3 35.56,90.3 35.31,90.55 35.31,99.06 36.32,100.08 40.89,100.08
GND on TOP (solid shape): 54.36,110.74 54.36,109.47 54.1,109.22 50.55,109.22 50.29,109.47 50.29,110.74 50.55,111 54.1,111
GND on TOP (solid shape): 65.79,107.95 65.79,106.68 64.52,105.41 63.5,105.41 63.25,105.66 63.25,106.43 63.5,106.68 64.26,106.68 64.52,106.93 64.52,107.95 64.77,108.2 65.53,108.2
GND on TOP (solid shape): 101.22,53.59 101.22,53.09 100.33,52.2 99.82,52.2 99.76,52.26 98.87,52.26 98.81,52.32 98.81,52.58 98.87,52.64 99.63,52.64 100.71,53.72 101.09,53.72
GND on TOP (solid shape): 182.5,12.7 182.5,9.27 182.25,9.02 181.1,9.02 180.85,9.27 180.85,10.03 180.47,10.41 180.47,12.7 180.72,12.95 182.25,12.95
GND on TOP (solid shape): 62.99,95.25 62.99,93.34 63.12,93.22 63.12,91.44 62.93,91.25 61.91,91.25 61.79,91.38 61.79,91.76 61.34,92.2 59.56,92.2 59.44,92.33 59.44,95.25 59.69,95.5 62.74,95.5
GND on TOP (solid shape): 96.27,58.55 96.27,54.23 96.52,53.98 97.41,53.98 97.54,53.85 97.54,52.89 97.54,52.88 97.54,52.45 97.41,52.32 94.23,52.32 93.85,52.7 93.85,58.55 93.98,58.67 96.14,58.67
GND on TOP (solid shape): 47.37,110.87 47.37,107.7 47.5,107.57 47.5,102.87 47.24,102.62 45.72,102.62 45.47,102.87 45.47,107.44 45.72,107.7 45.72,109.86 45.47,110.11 44.83,110.11 44.7,110.24 44.7,110.74 44.96,111 47.24,111
GND on TOP (solid shape): 47.75,68.33 47.75,65.28 47.5,65.02 41.27,65.02 40.26,64.01 37.59,64.01 37.47,64.14 37.47,64.77 36.58,65.66 36.58,66.14 36.68,66.24 40.59,66.24 41.15,66.8 41.15,68.33 41.27,68.45 47.62,68.45
GND on TOP (solid shape): 68.2,64.39 68.2,63.63 68.33,63.5 68.33,61.98 68.58,61.72 70.87,61.72 71.12,61.98 71.12,62.99 71.37,63.25 74.42,63.25 74.68,62.99 74.68,61.72 74.93,61.47 81.03,61.47 81.28,61.21 81.28,60.45 81.03,60.2 62.76,60.2 62.23,60.73 62.23,64.26 62.48,64.52 68.07,64.52
GND on BOTTOM (solid shape): 54.36,110.74 54.36,109.73 54.1,109.47 50.55,109.47 50.29,109.73 50.29,110.74 50.55,111 54.1,111
GND on BOTTOM (solid shape): 89.41,100.58 89.41,99.82 89.15,99.57 86.61,99.57 86.36,99.82 86.36,100.58 86.61,100.84 89.15,100.84
GND on BOTTOM (solid shape): 21.84,105.92 21.84,103.89 21.59,103.63 19.3,103.63 19.18,103.76 19.18,105.28 20.07,106.17 21.59,106.17
GND on BOTTOM (solid shape): 61.21,124.71 61.21,120.4 56.9,116.08 55.63,116.08 55.37,116.33 55.37,119.13 55.63,119.38 58.17,119.38 58.67,119.89 58.67,124.71 58.93,124.97 60.96,124.97
GND on BOTTOM (solid shape): 68.83,114.3 68.83,109.98 68.58,109.73 62.48,109.73 62.23,109.98 62.23,114.3 62.48,114.55 68.58,114.55
GND on BOTTOM (solid shape): 72.14,122.94 72.14,120.65 71.88,120.4 70.36,120.4 70.1,120.65 70.1,122.94 70.36,123.19 71.88,123.19
GND on BOTTOM (solid shape): 47.75,68.58 47.75,65.28 47.5,65.02 40.39,65.02 40.13,65.28 40.13,66.04 40.39,66.29 40.64,66.29 41.15,66.8 41.15,68.58 41.4,68.83 47.5,68.83
GND on BOTTOM (solid shape): 182.63,12.45 182.63,9.4 182.37,9.14 181.1,9.14 180.85,9.4 180.85,11.05 180.47,11.43 180.47,12.45 180.72,12.7 182.37,12.7
GND on BOTTOM (solid shape): 69.34,63.25 76.2,63.25 76.45,62.99 76.45,61.72 76.71,61.47 81.03,61.47 81.28,61.21 81.28,60.45 81.03,60.2 62.76,60.2 62.23,60.73 62.23,64.26 62.48,64.52 68.07,64.52
GND on BOTTOM (solid shape): 41.15,99.82 41.15,94.49 40.89,94.23 38.23,94.23 37.85,93.85 37.85,90.55 37.59,90.3 35.56,90.3 35.31,90.55 35.31,99.06 36.32,100.08 40.89,100.08
GND on BOTTOM (solid shape): 34.04,116.2 34.04,115.95 34.29,115.7 37.47,115.7 37.59,115.57 37.59,114.05 35.05,111.51 30.99,111.51 30.73,111.76 30.73,116.08 30.99,116.33 33.91,116.33
GND on BOTTOM (solid shape): 86.49,138.43 86.49,124.08 86.11,123.7 82.55,123.7 82.3,123.95 82.3,127.25 82.55,127.51 84.71,127.51 85.09,127.89 85.09,135.89 84.84,136.14 81.28,136.14 80.9,135.76 80.9,134.62 80.64,134.37 76.71,134.37 76.45,134.62 76.45,138.56 76.71,138.81 86.11,138.81
GND on TOP: 71.88,90.68 72.64,90.68 73.41,89.92 73.41,88.9 73.15,88.65 71.88,88.65 71.63,88.9 71.63,90.42
GND on TOP: 19.05,125.22 23.11,125.22 23.37,124.97 23.37,109.47 23.11,109.22 19.05,109.22 18.8,109.47 18.8,124.97
GND on TOP: 77.72,103.12 80.01,103.12 80.26,102.87 80.26,90.17 80.01,89.92 74.17,89.92 72.64,91.44 67.82,91.44 67.56,91.69 67.56,92.71 67.82,92.96 72.9,92.96 74.68,91.19 76.96,91.19 77.47,91.69 77.47,102.87
GND on TOP: 84.07,132.21 84.07,123.95 83.82,123.7 82.55,123.7 82.3,123.95 82.3,132.08 82.55,132.33 83.95,132.33
GND on TOP: 39.88,107.44 40.89,107.44 41.15,107.19 41.15,103.38 40.89,103.12 38.86,103.12 38.61,103.38 38.61,105.41 39.12,105.92 39.12,106.68
GND on TOP: 29.46,79.88 26.92,79.88 26.8,79.76 26.8,75.18 26.92,75.06 29.46,75.06 29.59,75.18 29.59,79.76
GND on TOP: 66.8,78.49 68.58,78.49 68.83,78.74 68.83,79.5 68.58,79.76 66.8,79.76 66.67,79.63 66.67,78.61
GND on TOP: 90.93,79.25 90.55,78.87 89.41,78.87 89.15,79.12 89.15,82.8 89.41,83.06 90.17,83.06 90.93,82.3
GND on TOP: 18.92,68.96 17.14,68.96 16.89,68.71 16.89,66.8 17.14,66.55 18.92,66.55 19.18,66.8 19.18,68.71
GND on TOP: 89.41,102.74 89.41,100.58 89.03,100.2 88.01,100.2 87.76,100.46 87.76,106.3 87.63,106.43 87.63,107.95 88.9,107.95 89.15,108.2 89.15,108.71 88.9,108.97 88.9,110.24 89.15,110.49 90.93,110.49 91.19,110.24 91.19,104.52
GND on TOP: 19.56,62.23 19.56,61.21 19.68,61.09 23.37,61.09 23.5,61.21 23.5,63.25 23.24,63.5 20.83,63.5
GND on TOP: 46.74,119.38 58.17,119.38 58.67,119.89 58.67,124.71 58.93,124.97 60.96,124.97 61.21,124.71 61.21,120.4 58.17,117.35 58.17,115.06 57.91,114.81 55.37,114.81 54.86,115.32 49.91,115.32 49.4,114.81 46.74,114.81 46.48,115.06 46.48,119.13
GND on TOP: 75.44,82.04 79.38,82.04 79.5,81.92 80.77,81.92 80.77,79.76 81.03,79.5 82.04,79.5 82.3,79.25 82.3,76.96 82.04,76.71 75.44,76.71 75.18,76.96 75.18,81.79
GND on BOTTOM: 74.93,112.78 77.47,112.78 77.72,112.52 77.72,112.01 78.23,111.51 78.23,110.24 77.98,109.98 74.93,109.98 74.68,109.73 74.68,108.46 74.42,108.2 73.41,108.2 73.15,108.46 73.15,111
GND on BOTTOM: 44.96,111 48.01,111 48.26,110.74 48.26,109.47 47.5,108.71 47.5,102.87 47.24,102.62 44.96,102.62 44.7,102.87 44.7,110.74
GND on BOTTOM: 19.56,62.23 19.56,61.21 19.68,61.09 23.37,61.09 23.5,61.21 23.5,63.25 23.24,63.5 20.83,63.5
GND on BOTTOM: 77.72,103.12 79.76,103.12 80.01,102.87 80.01,90.17 79.76,89.92 74.17,89.92 72.64,91.44 59.69,91.44 59.44,91.69 59.44,95.25 59.69,95.5 62.74,95.5 65.28,92.96 72.9,92.96 74.68,91.19 76.96,91.19 77.47,91.69 77.47,102.87
GND on BOTTOM: 40.89,107.44 41.15,107.19 41.15,103.38 40.89,103.12 38.86,103.12 38.61,103.38 38.61,107.19 38.86,107.44
GND on BOTTOM: 88.65,107.95 89.66,107.95 89.92,107.7 89.92,106.17 89.66,105.92 88.65,105.92 88.39,106.17 88.39,107.7
GND on BOTTOM: 19.81,125.22 23.11,125.22 23.37,124.97 23.37,109.47 23.11,109.22 19.81,109.22 19.56,109.47 19.56,124.97
GND on BOTTOM: 75.18,81.79 75.44,82.04 76.71,82.04 78.23,80.52 78.99,80.52 79.5,81.03 80.52,81.03 80.77,80.77 80.77,79.76 81.03,79.5 82.04,79.5 82.3,79.25 82.3,76.96 82.04,76.71 75.44,76.71 75.18,76.96
GND on L2-GND1: outline of 374 points within 2.03,1.02 188.98,138.98 ; 1 cut-out
GND on L3-IN1: 13.97,63.75 16,63.75 16.26,63.5 16.26,61.47 10.67,55.88 3.3,55.88 3.05,56.13 3.05,67.56 3.3,67.82 13.46,67.82 13.72,67.56 13.72,64.01
GND on L4-VCC1: 112.63,34.04 113.56,34.04 116.08,31.52 116.08,24.49 115.72,24.13 106.02,24.13 105.92,24.24 105.92,28.96 105.9,29.05 105.84,29.14 105.59,29.39 105.51,29.44 105.41,29.46 105.01,29.46 104.9,29.57 104.9,31.9 105.52,32.51 105.66,32.51 105.76,32.53 105.84,32.59 106.35,33.09 106.41,33.18 106.43,33.27 106.43,33.93 106.53,34.04 107.84,34.04 107.95,33.93 107.95,33.78 107.97,33.68 108.02,33.6 108.34,33.28 108.42,33.23 108.52,33.21 112.01,33.21 112.11,33.23 112.19,33.28 112.45,33.54 112.5,33.62 112.52,33.72 112.52,33.93
GND on L4-VCC1: 82.91,15.49 91.33,15.49 91.69,15.13 91.69,9.25 91.33,8.89 82.91,8.89 82.55,9.25 82.55,15.13
GND on L4-VCC1: 18.09,100.97 18.97,100.97 20.72,99.21 20.77,99.17 20.83,99.13 20.83,91.16 20.65,90.98 20.59,90.9 20.57,90.81 20.57,64.11 18.49,62.03 18.43,61.95 18.41,61.85 18.41,54.08 18.06,53.72 11.81,53.72 11.71,53.7 11.63,53.65 11.07,53.09 8.26,53.09 8.16,53.07 8.08,53.01 7.19,52.12 7.13,52.04 7.11,51.94 7.11,34.29 7.13,34.19 7.19,34.11 7.95,33.35 8.03,33.29 8.13,33.27 8.66,33.27 8.89,33.04 8.89,27.34 7.2,25.65 4.42,25.65 4.06,26.01 4.06,45.34 4.04,45.44 3.99,45.52 3.05,46.46 3.05,68.86 4.3,70.1 16.38,70.1 16.48,70.12 16.56,70.18 17.83,71.45 17.89,71.53 17.91,71.63 17.91,74.17 17.89,74.27 17.83,74.35 16.31,75.87 16.23,75.93 16.13,75.95 5.31,75.95 4.7,76.56 4.7,94.26 5.57,95.12 16.38,95.12 16.48,95.14 16.56,95.2 17.71,96.34 17.76,96.42 17.78,96.52 17.78,100.66
GND on L4-VCC1: 63.99,15.49 73.3,15.49 73.66,15.13 73.66,9.5 73.05,8.89 64.88,8.89 64.52,9.25 64.52,14.35 64.5,14.45 64.44,14.53 63.79,15.18 63.79,15.3
GND on L4-VCC1: outline of 85 points within 177.8,1.02 188.98,123.7
GND on L4-VCC1, L5-VCC2: 45.32,20.07 52.98,20.07 53.34,19.71 53.34,7.47 52.6,6.73 51.29,6.73 48.44,9.58 48.36,9.63 48.26,9.65 45.32,9.65 44.96,10.01 44.96,19.71
GND on L5-VCC2: 187.18,86.36 188.49,86.36 188.98,85.87 188.98,2 188.69,1.3 188,1.02 174.9,1.02 174.37,1.54 174.37,7.81 174.38,7.82 174.43,7.86 174.48,7.9 175.47,8.89 179.32,8.89 179.52,8.93 179.68,9.04 180.7,10.05 180.81,10.22 180.85,10.41 180.85,13.51 181.31,13.97 182.12,13.97 182.31,14.01 182.48,14.12 184.76,16.4 184.87,16.57 184.91,16.76 184.91,22.86 184.87,23.05 184.76,23.22 183.64,24.34 183.64,25.91 183.57,26.16 183.39,26.35 183.39,27.58 185.6,29.79 185.65,29.87 185.67,29.97 185.67,54.36 185.65,54.45 185.6,54.54 182.88,57.26 182.88,68.22 186.62,71.96 186.67,72.04 186.69,72.14 186.69,82.8 186.67,82.9 186.62,82.98 186.44,83.16 186.44,83.71 186.74,84.02 186.8,84.1 186.82,84.2 186.82,86
GND on L5-VCC2: 82.55,15.49 91.33,15.49 91.69,15.13 91.69,9.25 91.33,8.89 82.91,8.89 82.55,9.25
GND on L5-VCC2: 18.09,100.97 18.82,100.97 21.08,98.7 21.08,66.15 18.18,63.25 17.27,63.25 17.17,63.23 17.09,63.17 16.58,62.66 16.53,62.58 16.51,62.48 16.51,61.57 12.27,57.33 12.21,57.25 12.19,57.15 12.19,46.74 11.94,46.48 11.94,36.74 9.19,33.99 8.97,33.66 8.89,33.27 8.89,27.34 7.2,25.65 4.42,25.65 4.06,26.01 4.06,45.34 4.04,45.44 3.99,45.52 3.05,46.46 3.05,68.86 4.3,70.1 16.38,70.1 16.48,70.12 16.56,70.18 17.83,71.45 17.89,71.53 17.91,71.63 17.91,74.17 17.89,74.27 17.83,74.35 16.31,75.87 16.23,75.93 16.13,75.95 5.31,75.95 4.7,76.56 4.7,94.26 5.57,95.12 16.38,95.12 16.48,95.14 16.56,95.2 17.71,96.34 17.76,96.42 17.78,96.52 17.78,100.66
GND on L5-VCC2: 59.94,138.07 60.33,138.46 75.56,138.46 75.95,138.07 75.95,128.12 75.59,127.76 73.91,127.76 73.82,127.74 73.73,127.69 72.28,126.24 64.37,126.24 63.68,126.93 63.6,126.98 63.5,127 60.3,127 59.94,127.36
GND on L5-VCC2: 63.88,15.49 73.3,15.49 73.66,15.13 73.66,9.5 73.05,8.89 64.88,8.89 64.52,9.25 64.52,14.35 64.5,14.45 64.44,14.53 63.79,15.18 63.79,15.4
GND on L7-GND2: outline of 366 points within 3.05,1.02 188.98,138.98
GND_+3V3A_L on TOP (solid shape): 70.36,81.53 70.36,78.87 69.98,78.49 69.34,78.49 69.09,78.74 69.09,81.53 69.34,81.79 70.1,81.79
GND_+3V3A_L on TOP (solid shape): 74.55,85.47 74.55,84.33 74.42,84.2 70.36,84.2 70.1,84.45 70.1,85.6 74.42,85.6
GND_+3V3A_L on BOTTOM: 67.56,86.87 72.39,86.87 72.64,86.61 72.64,80.01 72.39,79.76 69.34,79.76 69.09,80.01 69.09,81.03 68.83,81.28 67.56,81.28 67.31,81.53 67.31,86.61
GND_EARTH on TOP: 9.4,132.33 8.64,131.57 1.78,131.57 1.02,132.33 1.02,132.84 1.02,137.92 2.03,138.94 8.89,138.94 9.4,138.43
GND_EARTH on BOTTOM: 2.08,138.98 17.99,138.98 18.8,138.18 18.8,120.65 17.78,119.63 12.45,119.63 9.4,116.59 5.08,116.59 4.57,117.09 4.57,119.13 5.33,119.89 8.64,119.89 9.91,121.16 9.91,127.51 10.67,128.27 10.67,130.81 9.91,131.57 1.78,131.57 1.02,132.33 1.02,137.92
GND_EARTH on L2-GND1: 1.02,138 1.3,138.7 2,138.98 19.56,138.98 20.07,138.47 20.07,127.72 17.93,125.58 17.82,125.42 17.78,125.22 17.78,119.84 17.57,119.63 12.7,119.63 12.51,119.6 12.34,119.49 9.44,116.59 5.04,116.59 4.57,117.05 4.57,119.17 5.29,119.89 8.38,119.89 8.58,119.93 8.74,120.04 9.76,121.05 9.87,121.22 9.91,121.41 9.91,127.55 10.52,128.16 10.63,128.33 10.67,128.52 10.67,130.56 10.63,130.75 10.52,130.92 10.01,131.42 9.85,131.53 9.65,131.57 1.73,131.57 1.02,132.29
GND_EARTH on L6-IN2: 1.52,138.43 18.54,138.43 18.8,138.18 18.8,120.65 17.78,119.63 12.45,119.63 9.4,116.59 5.08,116.59 4.57,117.09 4.57,119.13 5.33,119.89 8.64,119.89 9.91,121.16 9.91,127.51 10.67,128.27 10.67,130.81 9.91,131.57 1.52,131.57 1.02,132.08 1.02,137.92
GND_EARTH on L7-GND2: 1.02,138 1.3,138.7 2,138.98 18.03,138.98 18.8,138.22 18.8,120.61 17.82,119.63 12.7,119.63 12.51,119.6 12.34,119.49 9.44,116.59 5.04,116.59 4.57,117.05 4.57,119.17 5.29,119.89 8.38,119.89 8.58,119.93 8.74,120.04 9.76,121.05 9.87,121.22 9.91,121.41 9.91,127.55 10.52,128.16 10.63,128.33 10.67,128.52 10.67,130.56 10.63,130.75 10.52,130.92 10.01,131.42 9.85,131.53 9.65,131.57 1.73,131.57 1.02,132.29
GND_IC on L2-GND1, L4-VCC1, L5-VCC2, L7-GND2: 11.15,26.67 20.72,26.67 21.08,26.31 21.08,23.98 20.72,23.62 10.01,23.62 9.4,24.24 9.4,24.91
VBUS1_DUT_Q on TOP: 28.7,66.29 28.83,66.17 28.83,65.53 29.08,65.28 30.35,65.28 30.48,65.15 30.48,64.14 30.35,64.01 29.84,64.01 29.72,63.88 29.72,62.99 29.59,62.87 27.18,62.87 27.05,62.99 27.05,63.75 26.92,63.88 25.78,63.88 25.65,64.01 25.65,66.17 25.78,66.29
VBUS1_DUT_Q on BOTTOM: 29.34,66.29 28.57,66.29 28.45,66.42 27.94,66.42 27.81,66.29 26.54,66.29 26.42,66.17 26.42,62.99 26.54,62.87 30.35,62.87 30.48,62.99 30.48,65.15
VCC_DCIN on TOP (solid shape): 43.18,110.49 43.18,109.73 42.93,109.47 41.4,109.47 41.15,109.22 41.15,107.95 40.89,107.7 40.13,107.7 39.88,107.95 39.88,109.22 41.4,110.74 42.93,110.74
VCC_DCIN on TOP (solid shape): 58.17,137.67 58.17,120.14 57.91,119.89 48.64,119.89 48.64,119.93 48.26,120.27 47.88,119.93 47.88,119.89 45.97,119.89 45.72,119.63 45.72,114.81 43.69,112.78 43.05,112.78 42.93,112.9 42.93,115.32 43.18,115.57 44.7,115.57 45.09,115.95 45.09,121.67 44.96,121.79 44.96,125.73 45.21,125.98 48.77,125.98 49.53,126.75 49.53,137.67 49.78,137.92 57.91,137.92
VCC_DCIN on BOTTOM (solid shape): 43.18,110.49 43.18,107.95 42.93,107.7 40.13,107.7 39.88,107.95 39.88,109.47 41.15,110.74 42.93,110.74
VCC_DCIN on BOTTOM (solid shape): 58.17,137.67 58.17,120.14 57.91,119.89 49.02,119.89 48.26,120.65 48.26,121.16 48.01,121.41 45.85,121.41 44.96,122.3 44.96,125.48 45.21,125.73 48.51,125.73 49.53,126.75 49.53,137.67 49.78,137.92 57.91,137.92
VCC_DCIN on L4-VCC1: 44.81,138.32 44.85,138.37 44.89,138.43 58.7,138.43 59.05,138.08 59.05,120.25 58.44,119.63 44.81,119.63 44.45,119.99 44.45,137.97
VCC_DCIN on L5-VCC2: 44.45,137.97 44.95,138.47 59.05,138.46 59.44,138.07 59.44,120.25 58.82,119.63 51.56,119.63 51.46,119.61 51.38,119.56 50.62,118.8 50.57,118.72 50.55,118.62 50.55,116.95 42.31,108.71 39.98,108.71 39.62,109.07 39.62,109.77 44.3,114.45 44.41,114.61 44.45,114.81
VCC_DCIN+ on TOP: 20.07,137.92 20.07,127.76 17.78,125.48 17.78,108.46 17.53,108.2 10.92,108.2 9.14,109.98 9.14,111.51 7.87,112.78 5.59,112.78 4.57,113.79 4.57,115.06 5.08,115.57 7.37,115.57 7.87,116.08 7.87,119.13 9.91,121.16 9.91,123.44 10.67,124.21 10.67,137.92 10.92,138.18 19.81,138.18
VCC_DCIN+ on BOTTOM: 12.95,118.62 18.29,118.62 18.54,118.36 18.54,108.46 18.29,108.2 10.92,108.2 9.14,109.98 9.14,111.51 7.87,112.78 5.59,112.78 4.57,113.79 4.57,115.06 5.08,115.57 9.91,115.57
VCC_DCIN+ on L2-GND1, L7-GND2: 12.91,118.62 17.57,118.62 17.78,118.41 17.78,108.41 17.57,108.2 10.88,108.2 9.14,109.94 9.14,111.25 9.11,111.45 9,111.61 7.98,112.63 7.81,112.74 7.62,112.78 5.54,112.78 4.57,113.75 4.57,115.11 5.04,115.57 9.65,115.57 9.85,115.61 10.01,115.72
VCC_DCIN+ on L3-IN1: 7.37,115.57 7.87,116.08 7.87,119.13 10.67,121.92 10.67,137.92 10.92,138.18 19.81,138.18 20.07,137.92 20.07,127.76 17.78,125.48 17.78,108.46 17.53,108.2 10.92,108.2 9.14,109.98 9.14,111.51 7.87,112.78 5.59,112.78 4.57,113.79 4.57,115.06 5.08,115.57
VCC_DCIN+ on L4-VCC1: 11.13,138.43 42.99,138.43 43.03,138.37 43.07,138.32 43.43,137.97 43.43,108.41 42.57,107.55 42.46,107.38 42.42,107.19 42.42,103.99 42.06,103.63 38.86,103.63 38.67,103.59 38.5,103.48 35.1,100.08 21.29,100.08 19.56,101.81 19.56,107.19 19.52,107.38 19.41,107.55 18.9,108.06 18.74,108.17 18.54,108.2 10.88,108.2 9.14,109.94 9.14,111.25 9.11,111.45 9,111.61 7.98,112.63 7.81,112.74 7.62,112.78 5.54,112.78 4.57,113.75 4.57,119.17 5.29,119.89 8.38,119.89 8.58,119.93 8.74,120.04 9.76,121.05 9.87,121.22 9.91,121.41 9.91,127.55 10.52,128.16 10.63,128.33 10.67,128.52 10.67,137.97
VCC_DCIN+ on L5-VCC2: 11.03,138.32 11.09,138.39 11.13,138.47 42.93,138.47 43.43,137.97 43.43,115.02 38.76,110.34 38.65,110.18 38.61,109.98 38.61,107.14 33.32,101.85 32.89,101.85 32.7,101.82 32.53,101.71 30.9,100.08 21.29,100.08 19.45,101.92 19.53,102.07 19.56,102.23 19.56,107.19 19.52,107.38 19.41,107.55 18.9,108.06 18.74,108.17 18.54,108.2 10.88,108.2 9.14,109.94 9.14,111.25 9.11,111.45 9,111.61 7.98,112.63 7.81,112.74 7.62,112.78 5.54,112.78 4.57,113.75 4.57,119.17 5.29,119.89 8.38,119.89 8.58,119.93 8.74,120.04 9.76,121.05 9.87,121.22 9.91,121.41 9.91,127.55 10.52,128.16 10.63,128.33 10.67,128.52 10.67,137.97
VCC_DCIN+ on L6-IN2: 9.91,115.57 12.95,118.62 17.53,118.62 17.78,118.36 17.78,108.46 17.53,108.2 10.92,108.2 9.14,109.98 9.14,111.51 7.87,112.78 5.59,112.78 4.57,113.79 4.57,115.06 5.08,115.57
VCC_DCIN- on TOP: 1.27,130.56 8.64,130.56 8.89,130.3 8.89,121.67 8.13,120.9 4.83,120.9 3.56,119.63 3.56,113.28 5.08,111.76 7.37,111.76 8.13,111 8.13,109.47 10.41,107.19 18.29,107.19 18.54,106.93 18.54,102.49 18.03,101.98 1.78,101.98 1.78,101.98 1.02,102.74 1.02,130.3
VCC_DCIN- on BOTTOM: 1.27,130.56 9.4,130.56 9.65,130.3 9.65,128.78 8.89,128.02 8.89,121.67 8.13,120.9 4.83,120.9 3.56,119.63 3.56,113.28 5.08,111.76 7.37,111.76 8.13,111 8.13,109.47 10.41,107.19 18.29,107.19 18.54,106.93 18.54,102.49 18.03,101.98 1.78,101.98 1.02,102.74 1.02,130.3
VCC_DCIN- on L2-GND1, L7-GND2: 1.73,130.56 9.44,130.56 9.65,130.35 9.65,128.73 9.04,128.12 8.93,127.96 8.89,127.76 8.89,121.62 8.17,120.9 5.08,120.9 4.89,120.87 4.72,120.76 3.7,119.74 3.59,119.57 3.56,119.38 3.56,113.54 3.59,113.34 3.7,113.18 4.97,111.91 5.14,111.8 5.33,111.76 7.41,111.76 8.13,111.04 8.13,109.73 8.17,109.53 8.28,109.37 10.31,107.34 10.47,107.23 10.67,107.19 18.33,107.19 18.54,106.98 18.54,102.45 18.08,101.98 1.73,101.98 1.02,102.7 1.02,129.84
VCC_DCIN- on L3-IN1, L6-IN2: 1.27,130.56 8.64,130.56 8.89,130.3 8.89,121.67 8.13,120.9 4.83,120.9 3.56,119.63 3.56,113.28 5.08,111.76 7.37,111.76 8.13,111 8.13,109.47 10.41,107.19 18.29,107.19 18.54,106.93 18.54,102.49 18.03,101.98 1.78,101.98 1.02,102.74 1.02,130.3
VCC_DCIN- on L4-VCC1, L5-VCC2: 1.73,130.56 9.44,130.56 9.65,130.35 9.65,128.73 9.04,128.12 8.93,127.96 8.89,127.76 8.89,121.62 8.17,120.9 5.08,120.9 4.89,120.87 4.72,120.76 3.7,119.74 3.59,119.57 3.56,119.38 3.56,113.54 3.59,113.34 3.7,113.18 4.97,111.91 5.14,111.8 5.33,111.76 7.41,111.76 8.13,111.04 8.13,109.73 8.17,109.53 8.28,109.37 10.31,107.34 10.47,107.23 10.67,107.19 18.33,107.19 18.54,106.98 18.54,102.45 18.08,101.98 1.73,101.98 1.52,102.19 1.52,130.35
VCC_DCIN_Q on TOP: 53.47,111.51 45.97,111.51 45.85,111.63 45.85,113.03 46.1,113.28 48.77,113.28 49.4,113.92 49.4,114.43 49.78,114.81 53.34,114.81 53.59,114.55 53.59,111.63
VCC_DCIN_Q on BOTTOM: 54.61,118.36 54.86,118.11 54.86,115.82 53.34,114.3 53.34,111.76 53.09,111.51 45.97,111.51 45.72,111.76 45.72,113.16 45.97,113.41 48.9,113.41 49.53,114.05 49.53,115.06 51.05,116.59 51.05,117.98 51.44,118.36
VCC_DCIN_Q on L4-VCC1: 44.81,119.13 54.25,119.13 54.61,118.77 54.61,111.87 54.25,111.51 44.81,111.51 44.45,111.87 44.45,118.77
VCC_DCIN_Q on L5-VCC2: 51.67,119.13 54.25,119.13 54.61,118.77 54.61,111.61 54.5,111.51 46.84,111.51 46.74,111.61 46.74,112.42 50.98,116.66 51.03,116.74 51.05,116.84 51.05,118.51
VCC_SRC on TOP (solid shape): 64.77,127.51 64.77,122.68 68.83,118.62 68.83,115.32 68.58,115.06 64.77,115.06 64.26,114.55 64.26,108.71 64.01,108.46 61.47,108.46 60.45,109.47 55.37,109.47 55.12,109.73 55.12,114.05 55.37,114.3 58.17,114.3 58.67,114.81 58.67,117.09 61.72,120.14 61.72,126.49 61.98,126.75 63.5,126.75 63.75,127 63.75,127.51 64.01,127.76 64.52,127.76
VCC_SRC on BOTTOM (solid shape): 64.26,127 64.26,122.68 68.58,118.36 68.58,115.32 68.33,115.06 62.23,115.06 61.72,114.55 61.72,111.76 61.47,111.51 56.13,111.51 55.88,111.76 55.88,114.3 61.72,120.14 61.72,127 61.98,127.25 64.01,127.25
VCC_SRC on TOP: 80.64,82.55 75.18,82.55 74.93,82.8 74.93,86.11 75.18,86.36 77.85,86.36 77.98,86.23 77.98,84.58 79.5,83.06 80.64,83.06 80.77,82.93 80.77,82.68
VCC_SRC on TOP: 68.33,103.12 76.71,103.12 76.96,102.87 76.96,91.95 76.71,91.69 74.68,91.69 72.9,93.47 67.56,93.47 67.56,100.84 68.07,101.35 68.07,102.87
VCC_SRC on BOTTOM: 76.96,102.87 76.96,91.95 76.71,91.69 74.68,91.69 72.9,93.47 66.8,93.47 66.55,93.73 66.55,102.87 66.8,103.12 76.71,103.12
VCC_SRC on BOTTOM: 75.44,82.8 75.44,86.11 75.69,86.36 78.49,86.36 78.74,86.11 78.74,82.8 78.49,82.55 75.69,82.55
VCC_SRC on L4-VCC1: outline of 124 points within 55.12,76.45 156.21,138.43
VCC_SRC_FET on TOP (solid shape): 59.44,108.71 59.44,102.87 59.18,102.62 51.82,102.62 51.56,102.87 51.56,108.71 51.82,108.97 59.18,108.97
VCC_SRC_FET on BOTTOM (solid shape): 59.44,108.71 59.44,106.55 59.69,106.3 59.69,106.05 59.44,105.79 59.44,102.87 59.18,102.62 50.29,102.62 50.04,102.87 50.04,108.71 50.29,108.97 59.18,108.97
VCC_SRC_FET on TOP: 37.59,58.67 37.59,52.45 37.47,52.32 18.67,52.32 18.29,52.7 18.29,58.55 19.56,59.82 19.56,60.45 19.81,60.71 24.51,60.71 26.42,62.61 29.21,62.61 29.34,62.48 29.34,59.69 29.84,59.18 37.08,59.18
VCC_SRC_FET on BOTTOM: 37.59,58.67 37.59,53.21 37.34,52.96 35.94,52.96 35.31,52.32 27.18,52.32 26.67,51.82 26.16,52.32 18.67,52.32 18.29,52.7 18.29,58.55 19.56,59.82 19.56,60.45 19.81,60.71 24.51,60.71 26.42,62.61 29.21,62.61 29.34,62.48 29.34,59.69 29.84,59.18 37.08,59.18
VCC_SRC_FET on L4-VCC1: 51.41,106.43 58.19,106.43 58.55,106.07 58.55,91.67 58.06,91.19 51.56,91.19 51.46,91.17 51.38,91.11 46.56,86.29 46.5,86.2 46.48,86.11 46.48,82.4 46.12,82.04 37.34,82.04 37.24,82.02 37.16,81.97 35.38,80.19 35.33,80.11 35.31,80.01 35.31,78.49 35.33,78.39 35.38,78.31 35.69,78 35.69,66.55 35.71,66.45 35.76,66.37 39.12,63.01 39.12,55.22 37.61,53.72 19.28,53.72 18.92,54.08 18.92,61.74 21.01,63.83 21.06,63.91 21.08,64.01 21.08,90.7 21.26,90.88 21.32,90.96 21.34,91.06 21.34,98.83 21.57,99.06 35.31,99.06 35.5,99.1 35.67,99.21 39.07,102.62 43.33,102.62 43.51,102.44 43.59,102.38 43.69,102.36 49.53,102.36 49.63,102.38 49.71,102.44 50.47,103.2 50.53,103.28 50.55,103.38 50.55,105.56
